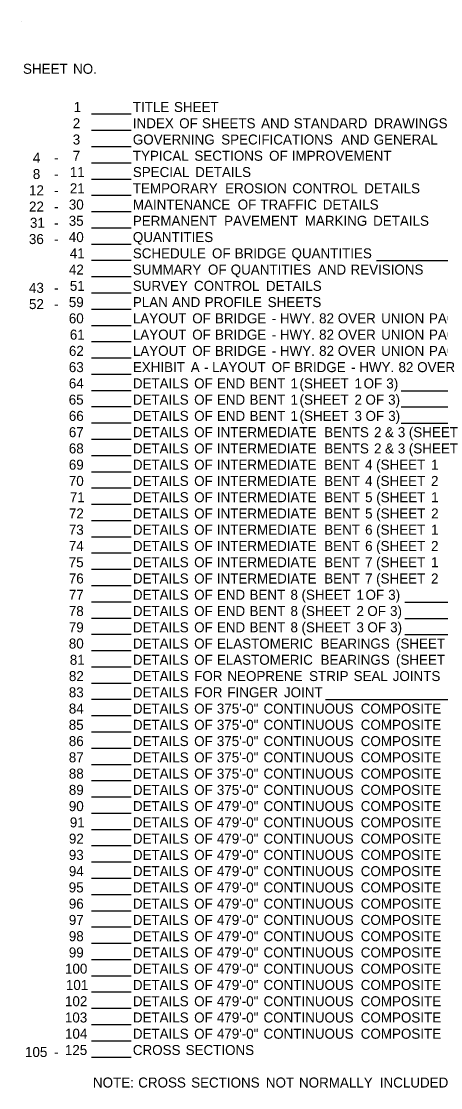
# Model space of a CAD drawing. Extents: x -1420 to 1630, y -1031 to 935.
# Drawn here: x -1420 to -917, y -754 to 525 of the extents above; entities that cross this region are included whole.
import ezdxf

# ---------------------------------------------------------------- set-up
doc = ezdxf.new("R2010")
doc.units = 0
doc.layers.add('Default', color=7, linetype='Continuous')

msp = doc.modelspace()

# ---------------------------------------------------------------- linework, layer by layer
at = {"layer": 'Default'}
for p, q in [((-1419.8, 525), (-1419.8, 525)), ((-1335.9, 413.9), (-1288.2, 413.9)), ((-1335.9, 394.4), (-1288.2, 394.4)), ((-1335.9, 374.9), (-1288.2, 374.9)), ((-1335.9, 355.4), (-1288.2, 355.4)), ((-1335.9, 335.9), (-1288.2, 335.9)), ((-1335.9, 316.4), (-1288.2, 316.4)), ((-1335.9, 296.9), (-1288.2, 296.9)), ((-1335.9, 277.4), (-1288.2, 277.4)), ((-1335.9, 257.9), (-1288.2, 257.9)), ((-1335.9, 238.4), (-1288.2, 238.4)), ((-994.1, 238), (-195.2, 238)), ((-1335.9, 218.9), (-1288.2, 218.9)), ((-1335.9, 199.4), (-1288.2, 199.4)), ((-1335.9, 179.9), (-1288.2, 179.9)), ((-1335.9, 160.4), (-1288.2, 160.4)), ((-1335.9, 140.9), (-1288.2, 140.9)), ((-1335.9, 121.4), (-1288.2, 121.4)), ((-1335.9, 101.9), (-1288.2, 101.9)), ((-1335.9, 82.4), (-1288.2, 82.4)), ((-964.8, 82), (-195.2, 82)), ((-1335.9, 62.9), (-1288.2, 62.9)), ((-964.8, 62.5), (-195.2, 62.5)), ((-1335.9, 43.4), (-1288.2, 43.4)), ((-964.8, 43), (-195.2, 43)), ((-1335.9, 23.9), (-1288.2, 23.9)), ((-1335.9, 4.4), (-1288.2, 4.4)), ((-1335.9, -15.1), (-1288.2, -15.1)), ((-1335.9, -34.6), (-1288.2, -34.6)), ((-1335.9, -54.1), (-1288.2, -54.1)), ((-1335.9, -73.6), (-1288.2, -73.6)), ((-1335.9, -93.1), (-1288.2, -93.1)), ((-1335.9, -112.6), (-1288.2, -112.6)), ((-1335.9, -132.1), (-1288.2, -132.1)), ((-1335.9, -151.6), (-1288.2, -151.6)), ((-1335.9, -171.1), (-1288.2, -171.1)), ((-960.5, -171.5), (-195.2, -171.5)), ((-1335.9, -190.6), (-1288.2, -190.6)), ((-960.5, -191), (-195.2, -191)), ((-1335.9, -210.1), (-1288.2, -210.1)), ((-960.5, -210.5), (-195.2, -210.5)), ((-1335.9, -229.6), (-1288.2, -229.6)), ((-1335.9, -249.1), (-1288.2, -249.1)), ((-1335.9, -268.6), (-1288.2, -268.6)), ((-1335.9, -288.1), (-1288.2, -288.1)), ((-1055.5, -288.5), (-195.2, -288.5)), ((-1335.9, -307.6), (-1288.2, -307.6)), ((-1335.9, -327.1), (-1288.2, -327.1)), ((-1335.9, -346.6), (-1288.2, -346.6)), ((-1335.9, -366.1), (-1288.2, -366.1)), ((-1335.9, -385.6), (-1288.2, -385.6)), ((-1335.9, -405.1), (-1288.2, -405.1)), ((-1335.9, -424.6), (-1288.2, -424.6)), ((-1335.9, -444.1), (-1288.2, -444.1)), ((-1335.9, -463.6), (-1288.2, -463.6)), ((-1335.9, -483.1), (-1288.2, -483.1)), ((-1335.9, -502.6), (-1288.2, -502.6)), ((-1335.9, -522.1), (-1288.2, -522.1)), ((-1335.9, -541.6), (-1288.2, -541.6)), ((-1335.9, -561.1), (-1288.2, -561.1)), ((-1335.9, -580.6), (-1288.2, -580.6)), ((-1335.9, -600.1), (-1288.2, -600.1)), ((-1335.9, -619.6), (-1288.2, -619.6)), ((-1335.9, -639.1), (-1288.2, -639.1)), ((-1335.9, -658.6), (-1288.2, -658.6)), ((-1335.9, -678.1), (-1288.2, -678.1)), ((-1335.9, -697.6), (-1288.2, -697.6)), ((-1335.9, -717.1), (-1288.2, -717.1))]:
    msp.add_line(p, q, dxfattribs=at)

# ---------------------------------------------------------------- texts
for s, p in [('SHEET', (-1417.8, 462.1)), (' NO.', (-1362.3, 462.1)), ('1', (-1357.1, 416.3)), ('TITLE', (-1286.2, 416.3)), (' SHEET', (-1241.4, 416.3)), ('2', (-1358.2, 396.8)), ('INDEX', (-1286.2, 396.8)), (' OF', (-1235.1, 396.8)), (' SHEETS', (-1207.9, 396.8)), (' AND', (-1137, 396.8)), (' STANDARD', (-1097.9, 396.8)), (' DRAWINGS', (-1001.9, 396.8)), ('3', (-1358.2, 377.3)), ('GOVERNING', (-1286.2, 377.3)), (' SPECIFICATIONS', (-1184.8, 377.3)), (' AND', (-1041.2, 377.3)), (' GENERAL', (-1002.1, 377.3)), ('4', (-1406, 355.4)), ('-', (-1380.4, 355.4)), ('7', (-1358.2, 357.8)), ('TYPICAL', (-1286.2, 357.8)), (' SECTIONS', (-1216.9, 357.8)), (' OF', (-1127.4, 357.8)), (' IMPROVEMENT', (-1100.2, 357.8)), ('8', (-1406, 335.9)), ('11', (-1361.7, 338.3)), ('SPECIAL', (-1286.2, 338.3)), (' DETAILS', (-1216, 338.3)), ('-', (-1380.4, 335.9)), ('12', (-1410.6, 316.4)), ('-', (-1380.4, 316.4)), ('21', (-1361.7, 318.8)), ('TEMPORARY', (-1286.2, 318.8)), (' EROSION', (-1180.1, 318.8)), (' CONTROL', (-1099.5, 318.8)), (' DETAILS', (-1013.5, 318.8)), ('22', (-1410.6, 296.9)), ('30', (-1362.9, 299.3)), ('MAINTENANCE', (-1286.2, 299.3)), (' OF', (-1165, 299.3)), (' TRAFFIC', (-1137.9, 299.3)), (' DETAILS', (-1063.1, 299.3)), ('-', (-1380.4, 296.9)), ('31', (-1409.5, 277.4)), ('-', (-1380.4, 277.4)), ('35', (-1363, 279.8)), ('PERMANENT', (-1286.2, 279.8)), (' PAVEMENT', (-1181.3, 279.8)), (' MARKING', (-1084.7, 279.8)), (' DETAILS', (-1002.8, 279.8)), ('36', (-1410.7, 257.9)), ('40', (-1362.9, 260.3)), ('QUANTITIES', (-1286.2, 260.3)), ('-', (-1380.4, 257.9)), ('41', (-1361.7, 240.8)), ('SCHEDULE', (-1286.2, 240.8)), (' OF', (-1195.8, 240.8)), (' BRIDGE', (-1168.6, 240.8)), (' QUANTITIES', (-1100.6, 240.8)), ('42', (-1362.8, 221.3)), ('SUMMARY', (-1286.2, 221.3)), (' OF', (-1200.6, 221.3)), (' QUANTITIES', (-1173.4, 221.3)), (' AND', (-1069, 221.3)), (' REVISIONS', (-1029.9, 221.3)), ('43', (-1410.7, 199.4)), ('-', (-1380.4, 199.4)), ('51', (-1361.7, 201.8)), ('SURVEY', (-1286.2, 201.8)), (' CONTROL', (-1217.4, 201.8)), (' DETAILS', (-1131.3, 201.8)), ('52', (-1410.6, 179.9)), ('59', (-1362.9, 182.3)), ('PLAN', (-1286.2, 182.3)), (' AND', (-1243.8, 182.3)), (' PROFILE', (-1204.6, 182.3)), (' SHEETS', (-1129.1, 182.3)), ('-', (-1380.4, 179.9)), ('60', (-1362.9, 162.8)), ('LAYOUT', (-1286.2, 162.8)), (' OF', (-1219.5, 162.8)), (' BRIDGE', (-1192.3, 162.8)), (' -', (-1124.2, 162.8)), (' HWY.', (-1114.5, 162.8)), (' 82', (-1067.5, 162.8)), (' OVER', (-1045.1, 162.8)), (' UNION', (-993.2, 162.8)), (' PACIFIC', (-935.9, 162.8)), ('61', (-1361.7, 143.3)), ('LAYOUT', (-1286.2, 143.3)), (' OF', (-1219.5, 143.3)), (' BRIDGE', (-1192.3, 143.3)), (' HWY.', (-1114.5, 143.3)), (' 82', (-1067.5, 143.3)), (' OVER', (-1045.1, 143.3)), (' UNION', (-993.2, 143.3)), (' PACIFIC', (-935.9, 143.3)), (' -', (-1124.2, 143.3)), ('62', (-1362.8, 123.8)), ('LAYOUT', (-1286.2, 123.8)), (' OF', (-1219.5, 123.8)), (' BRIDGE', (-1192.3, 123.8)), (' -', (-1124.2, 123.8)), (' HWY.', (-1114.5, 123.8)), (' 82', (-1067.5, 123.8)), (' OVER', (-1045.1, 123.8)), (' UNION', (-993.2, 123.8)), (' PACIFIC', (-935.9, 123.8)), ('63', (-1362.9, 104.3)), ('EXHIBIT', (-1286.2, 104.3)), (' A', (-1221.3, 104.3)), (' LAYOUT', (-1195.7, 104.3)), (' OF', (-1124.3, 104.3)), (' BRIDGE', (-1097.2, 104.3)), (' HWY.', (-1019.4, 104.3)), (' 82', (-972.4, 104.3)), (' OVER', (-950, 104.3)), (' -', (-1205.4, 104.3)), (' -', (-1029.1, 104.3)), ('64', (-1362.9, 84.8)), ('DETAILS', (-1286.2, 84.8)), (' OF', (-1217.2, 84.8)), (' END', (-1190, 84.8)), (' BENT', (-1150.9, 84.8)), (' 1', (-1101.8, 84.8)), (' (SHEET', (-1090.9, 84.8)), (' 1', (-1025.1, 84.8)), (' OF', (-1014.2, 84.8)), (' 3)', (-987, 84.8)), ('65', (-1363, 65.3)), ('DETAILS', (-1286.2, 65.3)), (' OF', (-1217.2, 65.3)), (' END', (-1190, 65.3)), (' BENT', (-1150.9, 65.3)), (' 1', (-1101.8, 65.3)), (' (SHEET', (-1090.9, 65.3)), (' 2', (-1025.1, 65.3)), (' OF', (-1012, 65.3)), (' 3)', (-984.8, 65.3)), ('66', (-1362.9, 45.8)), ('DETAILS', (-1286.2, 45.8)), (' OF', (-1217.2, 45.8)), (' END', (-1190, 45.8)), (' BENT', (-1150.9, 45.8)), (' 1', (-1101.8, 45.8)), (' (SHEET', (-1090.9, 45.8)), (' 3', (-1025.1, 45.8)), (' OF', (-1011.9, 45.8)), (' 3)', (-984.7, 45.8)), ('67', (-1362.9, 26.3)), ('DETAILS', (-1286.2, 26.3)), (' OF', (-1217.2, 26.3)), (' BENTS', (-1061.4, 26.3)), (' 2', (-1001.7, 26.3)), (' 3', (-973.2, 26.3)), (' (SHEET', (-960, 26.3)), (' INTERMEDIATE', (-1190, 26.3)), (' &', (-988.6, 26.3)), ('68', (-1362.9, 6.8)), ('DETAILS', (-1286.2, 6.8)), (' OF', (-1217.2, 6.8)), (' INTERMEDIATE', (-1190, 6.8)), (' BENTS', (-1061.4, 6.8)), (' 2', (-1001.7, 6.8)), (' &', (-988.6, 6.8)), (' 3', (-973.2, 6.8)), (' (SHEET', (-960, 6.8)), ('69', (-1362.9, -12.7)), ('DETAILS', (-1286.2, -12.7)), (' OF', (-1217.2, -12.7)), (' INTERMEDIATE', (-1190, -12.7)), (' BENT', (-1061.4, -12.7)), (' 4', (-1012.4, -12.7)), (' (SHEET', (-999.2, -12.7)), (' 1', (-933.4, -12.7)), ('70', (-1362.9, -32.2)), ('DETAILS', (-1286.2, -32.2)), (' OF', (-1217.2, -32.2)), (' INTERMEDIATE', (-1190, -32.2)), (' BENT', (-1061.4, -32.2)), (' 4', (-1012.4, -32.2)), (' (SHEET', (-999.2, -32.2)), (' 2', (-933.4, -32.2)), ('71', (-1361.7, -51.7)), ('DETAILS', (-1286.2, -51.7)), (' OF', (-1217.2, -51.7)), (' INTERMEDIATE', (-1190, -51.7)), (' BENT', (-1061.4, -51.7)), (' 5', (-1012.4, -51.7)), (' (SHEET', (-999.1, -51.7)), (' 1', (-933.3, -51.7)), ('72', (-1362.8, -71.2)), ('DETAILS', (-1286.2, -71.2)), (' OF', (-1217.2, -71.2)), (' INTERMEDIATE', (-1190, -71.2)), (' BENT', (-1061.4, -71.2)), (' 5', (-1012.4, -71.2)), (' (SHEET', (-999.1, -71.2)), (' 2', (-933.3, -71.2)), ('73', (-1362.9, -90.7)), ('DETAILS', (-1286.2, -90.7)), (' OF', (-1217.2, -90.7)), (' INTERMEDIATE', (-1190, -90.7)), (' BENT', (-1061.4, -90.7)), (' 6', (-1012.4, -90.7)), (' (SHEET', (-999.2, -90.7)), (' 1', (-933.4, -90.7)), ('74', (-1362.9, -110.2)), ('DETAILS', (-1286.2, -110.2)), (' OF', (-1217.2, -110.2)), (' INTERMEDIATE', (-1190, -110.2)), (' BENT', (-1061.4, -110.2)), (' 6', (-1012.4, -110.2)), (' (SHEET', (-999.2, -110.2)), (' 2', (-933.4, -110.2)), ('75', (-1363, -129.7)), ('DETAILS', (-1286.2, -129.7)), (' OF', (-1217.2, -129.7)), (' INTERMEDIATE', (-1190, -129.7)), (' BENT', (-1061.4, -129.7)), (' 7', (-1012.4, -129.7)), (' (SHEET', (-999.2, -129.7)), (' 1', (-933.4, -129.7)), ('76', (-1362.9, -149.2)), ('DETAILS', (-1286.2, -149.2)), (' OF', (-1217.2, -149.2)), (' INTERMEDIATE', (-1190, -149.2)), (' BENT', (-1061.4, -149.2)), (' 7', (-1012.4, -149.2)), (' (SHEET', (-999.2, -149.2)), (' 2', (-933.4, -149.2)), ('77', (-1362.9, -168.7)), ('DETAILS', (-1286.2, -168.7)), (' OF', (-1217.2, -168.7)), (' END', (-1190, -168.7)), (' BENT', (-1150.9, -168.7)), (' 8', (-1101.8, -168.7)), (' (SHEET', (-1088.6, -168.7)), (' 1', (-1022.8, -168.7)), (' OF', (-1011.9, -168.7)), (' 3)', (-984.7, -168.7)), ('78', (-1362.9, -188.2)), ('DETAILS', (-1286.2, -188.2)), (' OF', (-1217.2, -188.2)), (' END', (-1190, -188.2)), (' BENT', (-1150.9, -188.2)), (' 8', (-1101.8, -188.2)), (' (SHEET', (-1088.6, -188.2)), (' 2', (-1022.8, -188.2)), (' OF', (-1009.7, -188.2)), (' 3)', (-982.5, -188.2)), ('79', (-1362.9, -207.7)), ('DETAILS', (-1286.2, -207.7)), (' OF', (-1217.2, -207.7)), (' END', (-1190, -207.7)), (' BENT', (-1150.9, -207.7)), (' 8', (-1101.8, -207.7)), (' (SHEET', (-1088.6, -207.7)), (' 3', (-1022.8, -207.7)), (' OF', (-1009.6, -207.7)), (' 3)', (-982.4, -207.7)), ('80', (-1362.9, -227.2)), ('DETAILS', (-1286.2, -227.2)), (' OF', (-1217.2, -227.2)), (' ELASTOMERIC', (-1190, -227.2)), (' BEARINGS', (-1065.8, -227.2)), (' (SHEET', (-975.4, -227.2)), ('81', (-1361.7, -246.7)), ('DETAILS', (-1286.2, -246.7)), (' OF', (-1217.2, -246.7)), (' ELASTOMERIC', (-1190, -246.7)), (' BEARINGS', (-1065.8, -246.7)), (' (SHEET', (-975.4, -246.7)), ('82', (-1362.8, -266.2)), ('DETAILS', (-1286.2, -266.2)), (' FOR', (-1217.2, -266.2)), (' NEOPRENE', (-1177.4, -266.2)), (' STRIP', (-1079.5, -266.2)), (' SEAL', (-1026.2, -266.2)), (' JOINTS', (-979.3, -266.2)), ('83', (-1362.9, -285.7)), ('DETAILS', (-1286.2, -285.7)), (' FOR', (-1217.2, -285.7)), (' FINGER', (-1177.4, -285.7)), (' JOINT', (-1109.6, -285.7)), ('84', (-1362.9, -305.2)), ('DETAILS', (-1286.2, -305.2)), (' OF', (-1217.2, -305.2)), (' 375\'-0"', (-1190, -305.2)), (' CONTINUOUS', (-1134.1, -305.2)), (' COMPOSITE', (-1017.6, -305.2)), ('85', (-1363, -324.7)), ('DETAILS', (-1286.2, -324.7)), (' OF', (-1217.2, -324.7)), (' 375\'-0"', (-1190, -324.7)), (' CONTINUOUS', (-1134.1, -324.7)), (' COMPOSITE', (-1017.6, -324.7)), ('86', (-1362.9, -344.2)), ('DETAILS', (-1286.2, -344.2)), (' OF', (-1217.2, -344.2)), (' 375\'-0"', (-1190, -344.2)), (' CONTINUOUS', (-1134.1, -344.2)), (' COMPOSITE', (-1017.6, -344.2)), ('87', (-1362.9, -363.7)), ('DETAILS', (-1286.2, -363.7)), (' OF', (-1217.2, -363.7)), (' 375\'-0"', (-1190, -363.7)), (' CONTINUOUS', (-1134.1, -363.7)), (' COMPOSITE', (-1017.6, -363.7)), ('88', (-1362.9, -383.2)), ('DETAILS', (-1286.2, -383.2)), (' OF', (-1217.2, -383.2)), (' 375\'-0"', (-1190, -383.2)), (' CONTINUOUS', (-1134.1, -383.2)), (' COMPOSITE', (-1017.6, -383.2)), ('89', (-1362.9, -402.7)), ('DETAILS', (-1286.2, -402.7)), (' OF', (-1217.2, -402.7)), (' 375\'-0"', (-1190, -402.7)), (' CONTINUOUS', (-1134.1, -402.7)), (' COMPOSITE', (-1017.6, -402.7)), ('90', (-1362.9, -422.2)), ('DETAILS', (-1286.2, -422.2)), (' OF', (-1217.2, -422.2)), (' 479\'-0"', (-1190, -422.2)), (' CONTINUOUS', (-1134.1, -422.2)), (' COMPOSITE', (-1017.6, -422.2)), ('91', (-1361.7, -441.7)), ('DETAILS', (-1286.2, -441.7)), (' OF', (-1217.2, -441.7)), (' 479\'-0"', (-1190, -441.7)), (' CONTINUOUS', (-1134.1, -441.7)), (' COMPOSITE', (-1017.6, -441.7)), ('92', (-1362.8, -461.2)), ('DETAILS', (-1286.2, -461.2)), (' OF', (-1217.2, -461.2)), (' 479\'-0"', (-1190, -461.2)), (' CONTINUOUS', (-1134.1, -461.2)), (' COMPOSITE', (-1017.6, -461.2)), ('93', (-1362.9, -480.7)), ('DETAILS', (-1286.2, -480.7)), (' OF', (-1217.2, -480.7)), (' 479\'-0"', (-1190, -480.7)), (' CONTINUOUS', (-1134.1, -480.7)), (' COMPOSITE', (-1017.6, -480.7)), ('94', (-1362.9, -500.2)), ('DETAILS', (-1286.2, -500.2)), (' OF', (-1217.2, -500.2)), (' 479\'-0"', (-1190, -500.2)), (' CONTINUOUS', (-1134.1, -500.2)), (' COMPOSITE', (-1017.6, -500.2)), ('95', (-1363, -519.7)), ('DETAILS', (-1286.2, -519.7)), (' OF', (-1217.2, -519.7)), (' 479\'-0"', (-1190, -519.7)), (' CONTINUOUS', (-1134.1, -519.7)), (' COMPOSITE', (-1017.6, -519.7)), ('96', (-1362.9, -539.2)), ('DETAILS', (-1286.2, -539.2)), (' OF', (-1217.2, -539.2)), (' 479\'-0"', (-1190, -539.2)), (' CONTINUOUS', (-1134.1, -539.2)), (' COMPOSITE', (-1017.6, -539.2)), ('97', (-1362.9, -558.7)), ('DETAILS', (-1286.2, -558.7)), (' OF', (-1217.2, -558.7)), (' 479\'-0"', (-1190, -558.7)), (' CONTINUOUS', (-1134.1, -558.7)), (' COMPOSITE', (-1017.6, -558.7)), ('98', (-1362.9, -578.2)), ('DETAILS', (-1286.2, -578.2)), (' OF', (-1217.2, -578.2)), (' 479\'-0"', (-1190, -578.2)), (' CONTINUOUS', (-1134.1, -578.2)), (' COMPOSITE', (-1017.6, -578.2)), ('99', (-1362.9, -597.7)), ('DETAILS', (-1286.2, -597.7)), (' OF', (-1217.2, -597.7)), (' 479\'-0"', (-1190, -597.7)), (' CONTINUOUS', (-1134.1, -597.7)), (' COMPOSITE', (-1017.6, -597.7)), ('100', (-1367.5, -617.2)), ('DETAILS', (-1286.2, -617.2)), (' OF', (-1217.2, -617.2)), (' 479\'-0"', (-1190, -617.2)), (' CONTINUOUS', (-1134.1, -617.2)), (' COMPOSITE', (-1017.6, -617.2)), ('101', (-1366.4, -636.7)), ('DETAILS', (-1286.2, -636.7)), (' OF', (-1217.2, -636.7)), (' 479\'-0"', (-1190, -636.7)), (' CONTINUOUS', (-1134.1, -636.7)), (' COMPOSITE', (-1017.6, -636.7)), ('102', (-1367.5, -656.2)), ('DETAILS', (-1286.2, -656.2)), (' OF', (-1217.2, -656.2)), (' 479\'-0"', (-1190, -656.2)), (' CONTINUOUS', (-1134.1, -656.2)), (' COMPOSITE', (-1017.6, -656.2)), ('103', (-1367.6, -675.7)), ('DETAILS', (-1286.2, -675.7)), (' OF', (-1217.2, -675.7)), (' 479\'-0"', (-1190, -675.7)), (' CONTINUOUS', (-1134.1, -675.7)), (' COMPOSITE', (-1017.6, -675.7)), ('104', (-1367.5, -695.2)), ('DETAILS', (-1286.2, -695.2)), (' OF', (-1217.2, -695.2)), (' 479\'-0"', (-1190, -695.2)), (' CONTINUOUS', (-1134.1, -695.2)), (' COMPOSITE', (-1017.6, -695.2)), ('125', (-1367.6, -714.7)), ('CROSS', (-1286.2, -714.7)), (' SECTIONS', (-1227.4, -714.7)), ('105', (-1415.4, -717.1)), ('-', (-1380.4, -717.1)), ('NOTE:', (-1334, -753.7)), (' CROSS', (-1284.2, -753.7)), (' SECTIONS', (-1220.8, -753.7)), (' NOT', (-1131.3, -753.7)), (' NORMALLY', (-1091.6, -753.7)), (' INCLUDED', (-994.8, -753.7))]:
    msp.add_text(s, height=12, dxfattribs=at).set_placement(p)

doc.saveas('drawing.dxf')
